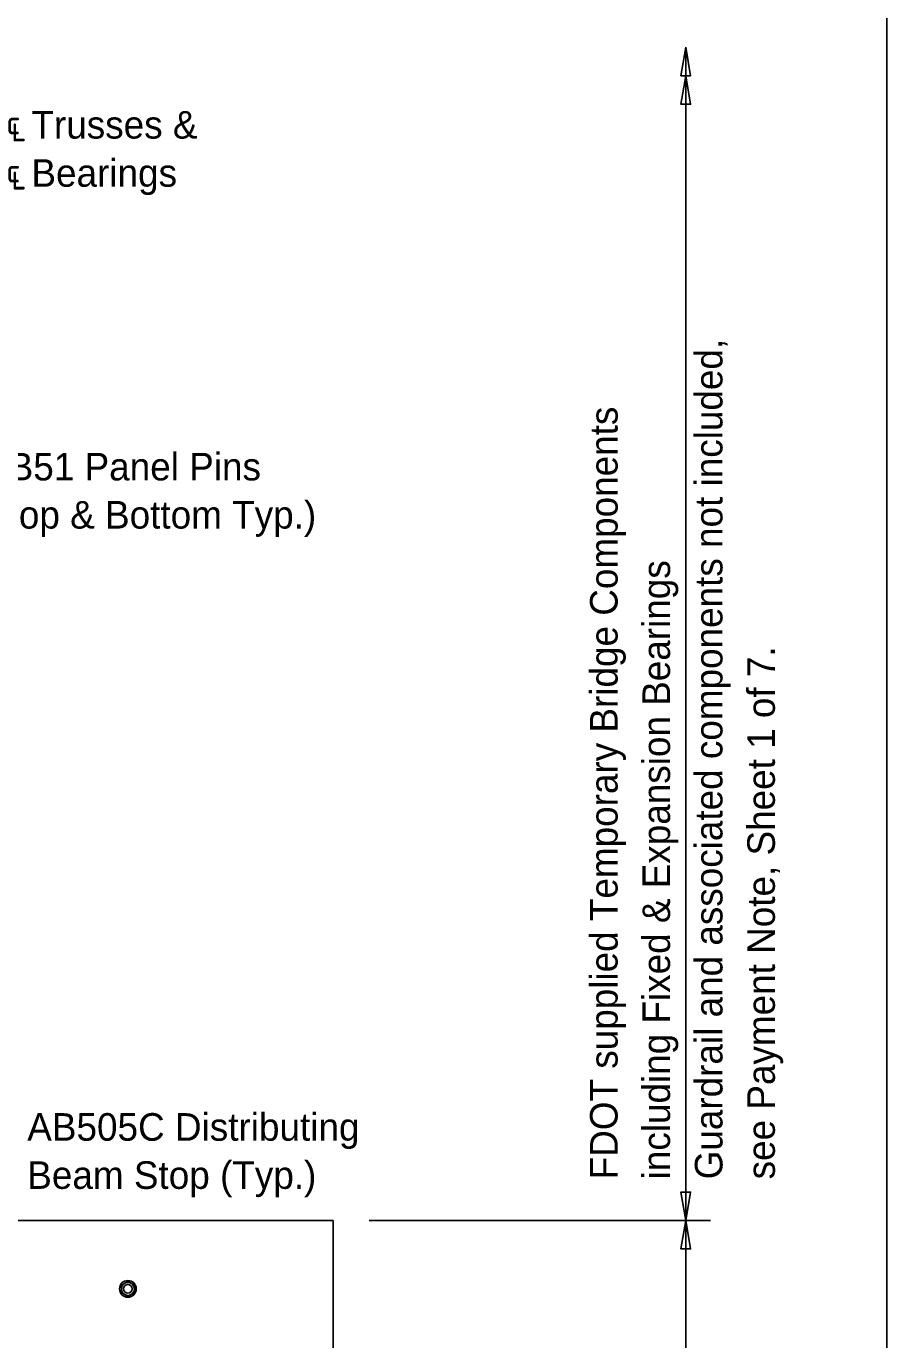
# Model space of a CAD drawing. Extents: x 11137.4 to 11208.2, y 76297.7 to 76332.4.
# Drawn here: x 11172.2 to 11178.49, y 76316.8 to 76326.4 of the extents above; entities that cross this region are included whole.
import ezdxf

# ---------------------------------------------------------------- set-up
doc = ezdxf.new("R2010")
doc.units = 0
for name, color, linetype in [('ActivePts-ConstElements', 7, 'Continuous'), ('Dimension', 7, 'Continuous'), ('SteelMisc', 7, 'Continuous'), ('TextStructures', 7, 'Continuous'), ('Wood', 7, 'Continuous')]:
    doc.layers.add(name, color=color, linetype=linetype)

msp = doc.modelspace()

# ---------------------------------------------------------------- linework, layer by layer
at = {"layer": 'ActivePts-ConstElements'}
msp.add_lwpolyline([(11137.4391, 76306.2133), (11178.4897, 76306.2133), (11178.4897, 76332.1594), (11137.4391, 76332.1594)], close=True, dxfattribs=at)
at = {"layer": 'Dimension'}
for p, q in [((11177.0215, 76307.8268), (11177.0215, 76326.2497)), ((11174.709, 76317.6731), (11177.2023, 76317.6731))]:
    msp.add_line(p, q, dxfattribs=at)
for points in [[(11177.0215, 76326.2497), (11176.9862, 76326.0415), (11177.0568, 76326.0415)], [(11177.0215, 76326.0415), (11176.9862, 76325.8332), (11177.0568, 76325.8332)], [(11177.0215, 76317.6731), (11176.9862, 76317.8813), (11177.0568, 76317.8813)], [(11177.0215, 76317.6731), (11176.9862, 76317.4648), (11177.0568, 76317.4648)]]:
    msp.add_lwpolyline(points, close=True, dxfattribs=at)
at = {"layer": 'SteelMisc'}
msp.add_lwpolyline([(11172.993, 76317.2004), (11172.993, 76317.1457), (11172.9456, 76317.1184), (11172.8983, 76317.1457), (11172.8983, 76317.2004), (11172.9456, 76317.2278)], close=True, dxfattribs=at)
for radius in [0.0612, 0.0474, 0.0312]:
    msp.add_circle((11172.9456, 76317.1731), radius, dxfattribs=at)
at = {"layer": 'Wood'}
for p, q in [((11174.4456, 76317.6731), (11156.9456, 76317.6731)), ((11174.4456, 76316.6731), (11174.4456, 76317.6731))]:
    msp.add_line(p, q, dxfattribs=at)

# ---------------------------------------------------------------- texts
at = {"layer": 'Dimension'}
for s, p in [('℄ Trusses & ', (11172.0565, 76325.5822)), ('℄ Bearings ', (11172.0565, 76325.2301)), ('AB505C Distributing ', (11172.2103, 76318.2562)), ('Beam Stop (Typ.)', (11172.2103, 76317.9042))]:
    msp.add_text(s, height=0.2016, dxfattribs=at).set_placement(p)
at = {"layer": 'TextStructures'}
for s, p in [('Guardrail and associated components not included,', (11177.2897, 76317.9739)), ('FDOT supplied Temporary Bridge Components ', (11176.5236, 76317.9739)), ('including Fixed & Expansion Bearings', (11176.9067, 76317.9739)), ('see Payment Note, Sheet 1 of 7.', (11177.6727, 76317.9739))]:
    msp.add_text(s, height=0.2016, rotation=90, dxfattribs=at).set_placement(p)
for s, p in [('AB51 Panel Pins ', (11171.8946, 76323.0832)), ('(Top & Bottom Typ.)', (11171.8946, 76322.7312))]:
    msp.add_text(s, height=0.2016, dxfattribs=at).set_placement(p)

doc.saveas('drawing.dxf')
